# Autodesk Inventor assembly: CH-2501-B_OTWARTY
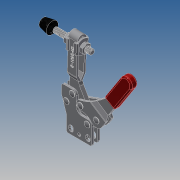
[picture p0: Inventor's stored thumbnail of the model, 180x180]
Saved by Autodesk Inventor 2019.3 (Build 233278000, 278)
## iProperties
Company: Î¢ÈíÖÐ¹ú
Created: 2012-09
Part Number: CH-2501-B_OTWARTY
Material: Ogólny
Description: STEP AP203
Document SubType Name: Assembly
Designer: CADENGINEERING4
Sending System: SolidWorks 2010
Preprocessor: SwSTEP 2.0
Title: CH-2501-B.STEP
Author: Î¢ÈíÓÃ»§
Revision Number: ÈÎºÎ
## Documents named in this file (12)
- E:\STRONA\Horizontal toggle clamp\CH-2501-B\CH-2501-B_OTWARTY.iam
- E:\STRONA\Horizontal toggle clamp\CH-2501-B\CH-FC-56300-02____1.ipt
- E:\STRONA\Horizontal toggle clamp\CH-2501-B\CH-FC-56300____1.ipt
- E:\STRONA\Horizontal toggle clamp\CH-2501-B\CH-2500-04____1.ipt
- E:\STRONA\Horizontal toggle clamp\CH-2501-B\CH-36092M-06____1.ipt
- E:\STRONA\Horizontal toggle clamp\CH-2501-B\CH-2501-B-02___.ipt
- E:\STRONA\Horizontal toggle clamp\CH-2501-B\CH-2500-05____1.ipt
- E:\STRONA\Horizontal toggle clamp\CH-2501-B\CH-2500-06____1.ipt
- E:\STRONA\Horizontal toggle clamp\CH-2501-B\FW516____1.ipt
- E:\STRONA\Horizontal toggle clamp\CH-2501-B\CH-2500-03____1.ipt
- E:\STRONA\Horizontal toggle clamp\CH-2501-B\CH-11401-05____1.ipt
- E:\STRONA\Horizontal toggle clamp\CH-2501-B\CH-2501-B-01___.ipt
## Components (20 placed, 20 different names)
1. CH-FC-56300-02____1_1 — Zestawiające:7, Zestawiające:8, Równoległe:2
2. CH-FC-56300____1_2 — Zestawiające:3, Zestawiające:4, Zestawiające:6, Zestawiające:7, Równoległe:2, Zestawiające:11
3. CH-2500-04____1_3 — Zestawiające:22, Zestawiające:23, Zestawiające:24, Równoległe:3, Zestawiające:25
4. CH-36092M-06____1_4 — Zestawiające:18, Zestawiające:19
5. CH-2501-B-02____5 — Zestawiające:2, Zestawiające:9, Zestawiające:10, Zestawiające:11, Zestawiające:37, Zestawiające:38, Zestawiające:39
6. CH-2500-05____1_6 — Zestawiające:1, Zestawiające:12, Zestawiające:13
7. CH-2500-06____1_7 — Zestawiające:35, Zestawiające:36, Zestawiające:38
8. FW516____1_8 — Zestawiające:2, Równoległe:1, Zestawiające:6, Zestawiające:8, Zestawiające:10
9. CH-FC-56300-02____1_9 — Zestawiające:3, Zestawiające:5
10. CH-2500-03____1_10 — Zestawiające:1, Zestawiające:12, Zestawiające:13, Zestawiające:14, Zestawiające:15, Zestawiające:16, Zestawiające:17, Zestawiające:25, Zestawiające:26, Zestawiające:27, Zestawiające:28, Przejściowe:1
11. CH-11401-05____1_11 — Zestawiające:29, Zestawiające:30
12. CH-2500-06____1_12 — Zestawiające:20, Zestawiające:21, Zestawiające:23
13. FW516____1_13 — Równoległe:1, Zestawiające:4, Zestawiające:5, Zestawiające:9
14. CH-2500-06____1_14 — Zestawiające:16, Zestawiające:17, Zestawiające:39
15. CH-36092M-06____1_15 — Zestawiające:14, Zestawiające:15
16. CH-2501-B-01____16 — Zestawiające:18, Zestawiające:19, Zestawiające:20, Zestawiające:21, Zestawiające:22, Zestawiające:29, Zestawiające:30, Zestawiające:31, Zestawiające:32, Zestawiające:33, Zestawiające:34, Zestawiające:35, Zestawiające:36, Zestawiające:37, Przejściowe:1
17. CH-2500-06____1_17 — Zestawiające:31, Zestawiające:32
18. CH-2500-06____1_18 — Zestawiające:27, Zestawiające:28
19. CH-36092M-06____1_19 — Zestawiające:24, Równoległe:3, Zestawiające:26
20. CH-36092M-06____1_20 — Zestawiające:33, Zestawiające:34
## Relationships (43: Mate 39, Flush 3, Transitional 1)
- Zestawiające:1 [Mate]: CH-2500-05____1_6 ↔ CH-2500-03____1_10
- Zestawiające:2 [Mate]: CH-2501-B-02____5 ↔ FW516____1_8
- Równoległe:1 [Flush]: FW516____1_8 ↔ FW516____1_13
- Zestawiające:3 [Mate]: CH-FC-56300____1_2 ↔ CH-FC-56300-02____1_9
- Zestawiające:4 [Mate]: CH-FC-56300____1_2 ↔ FW516____1_13
- Zestawiające:5 [Mate]: CH-FC-56300-02____1_9 ↔ FW516____1_13
- Zestawiające:6 [Mate]: CH-FC-56300____1_2 ↔ FW516____1_8
- Zestawiające:7 [Mate]: CH-FC-56300-02____1_1 ↔ CH-FC-56300____1_2
- Zestawiające:8 [Mate]: CH-FC-56300-02____1_1 ↔ FW516____1_8
- Zestawiające:9 [Mate]: CH-2501-B-02____5 ↔ FW516____1_13
- Zestawiające:10 [Mate]: CH-2501-B-02____5 ↔ FW516____1_8
- Równoległe:2 [Flush]: CH-FC-56300-02____1_1 ↔ CH-FC-56300____1_2
- Zestawiające:11 [Mate]: CH-FC-56300____1_2 ↔ CH-2501-B-02____5
- Zestawiające:12 [Mate]: CH-2500-05____1_6 ↔ CH-2500-03____1_10
- Zestawiające:13 [Mate]: CH-2500-05____1_6 ↔ CH-2500-03____1_10
- Zestawiające:14 [Mate]: CH-2500-03____1_10 ↔ CH-36092M-06____1_15
- Zestawiające:15 [Mate]: CH-2500-03____1_10 ↔ CH-36092M-06____1_15
- Zestawiające:16 [Mate]: CH-2500-03____1_10 ↔ CH-2500-06____1_14
- Zestawiające:17 [Mate]: CH-2500-03____1_10 ↔ CH-2500-06____1_14
- Zestawiające:18 [Mate]: CH-36092M-06____1_4 ↔ CH-2501-B-01____16
- Zestawiające:19 [Mate]: CH-36092M-06____1_4 ↔ CH-2501-B-01____16
- Zestawiające:20 [Mate]: CH-2500-06____1_12 ↔ CH-2501-B-01____16
- Zestawiające:21 [Mate]: CH-2500-06____1_12 ↔ CH-2501-B-01____16
- Zestawiające:22 [Mate]: CH-2500-04____1_3 ↔ CH-2501-B-01____16
- Zestawiające:23 [Mate]: CH-2500-04____1_3 ↔ CH-2500-06____1_12
- Zestawiające:24 [Mate]: CH-2500-04____1_3 ↔ CH-36092M-06____1_19
- Równoległe:3 [Flush]: CH-2500-04____1_3 ↔ CH-36092M-06____1_19
- Zestawiające:25 [Mate]: CH-2500-04____1_3 ↔ CH-2500-03____1_10
- Zestawiające:26 [Mate]: CH-2500-03____1_10 ↔ CH-36092M-06____1_19
- Zestawiające:27 [Mate]: CH-2500-03____1_10 ↔ CH-2500-06____1_18
- Zestawiające:28 [Mate]: CH-2500-03____1_10 ↔ CH-2500-06____1_18
- Zestawiające:29 [Mate]: CH-11401-05____1_11 ↔ CH-2501-B-01____16
- Zestawiające:30 [Mate]: CH-11401-05____1_11 ↔ CH-2501-B-01____16
- Zestawiające:31 [Mate]: CH-2501-B-01____16 ↔ CH-2500-06____1_17
- Zestawiające:32 [Mate]: CH-2501-B-01____16 ↔ CH-2500-06____1_17
- Zestawiające:33 [Mate]: CH-2501-B-01____16 ↔ CH-36092M-06____1_20
- Zestawiające:34 [Mate]: CH-2501-B-01____16 ↔ CH-36092M-06____1_20
- Zestawiające:35 [Mate]: CH-2500-06____1_7 ↔ CH-2501-B-01____16
- Zestawiające:36 [Mate]: CH-2500-06____1_7 ↔ CH-2501-B-01____16
- Zestawiające:37 [Mate]: CH-2501-B-02____5 ↔ CH-2501-B-01____16
- Zestawiające:38 [Mate]: CH-2501-B-02____5 ↔ CH-2500-06____1_7
- Zestawiające:39 [Mate]: CH-2501-B-02____5 ↔ CH-2500-06____1_14
- Przejściowe:1 [Transitional]: CH-2500-03____1_10 ↔ CH-2501-B-01____16
